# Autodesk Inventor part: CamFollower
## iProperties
Author: Administrator
Shininess: 41.0
PropertySet Name: _Private Model Information
Created: 2001-05
Part Number: CamFollower
Document SubType Name: Modeling
Designer: Administrator
Control State: 0
Master: False
Checked Out: False
PropertySet Name: Design Tracking Control
Density: 0.0
Volumn: 0.0
Area: 0.0
PropertySet Name: Model Information
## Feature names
1. Revolution5
2. OuterRace [Revolution]
3. CenterBody [Revolution]
4. HexCut [Extrusion]
5. Revolution6
6. Slot [Extrusion]
7. Eccentric2 [Revolution]
8. Revolution8
